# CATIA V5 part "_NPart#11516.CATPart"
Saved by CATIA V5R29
Part number: evaparat? 2
Revision: HERHANG?
Definition: B??MEYEN
Nomenclature: evaparat? 2
Source: Unknown
Bounding box of the stored display mesh (mm): x -47.577 to 809.625, y -15.875 to 142.875, z -15.875 to 460.375
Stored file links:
  C:\가치같이\SmartFactory_Freeze dryer\_NPart#11516.CATPart
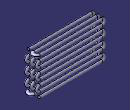
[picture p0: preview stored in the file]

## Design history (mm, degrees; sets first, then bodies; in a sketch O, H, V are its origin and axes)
Body1 "??k1" (main body)
  Solid1: solid without history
